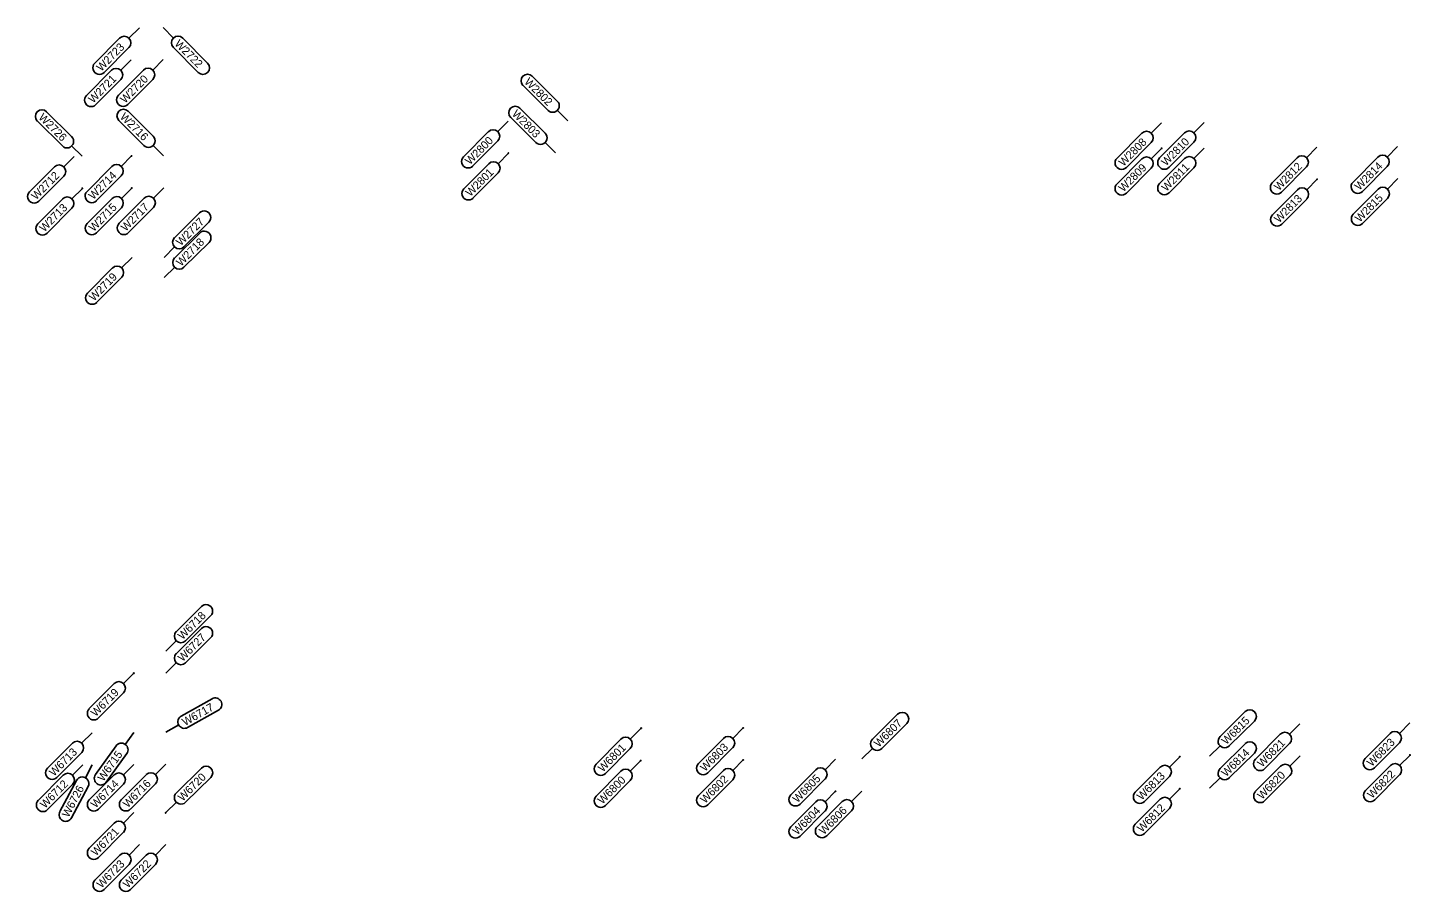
# Model space of a CAD drawing. Extents: x 12479652 to 12487250, y 9842710 to 9846560.
# Drawn here: x 12484644.7 to 12484860.6, y 9842742.5 to 9842877.4 of the extents above; entities that cross this region are included whole.
import ezdxf

# ---------------------------------------------------------------- set-up
doc = ezdxf.new("R2010")
doc.units = 0
doc.layers.add('_CIVIL_CONSTRUCTION', color=7, linetype='Continuous')
doc.layers.add('TextAlignmentLrg', color=7, linetype='Continuous')

msp = doc.modelspace()

# ---------------------------------------------------------------- linework, layer by layer
at = {"layer": '_CIVIL_CONSTRUCTION'}
for p, q in [((12484662.12, 9842877.34), (12484660.49, 9842875.71)), ((12484665.82, 9842877.36), (12484667.44, 9842875.72)), ((12484655.15, 9842871.79), (12484659.04, 9842875.7)), ((12484672.78, 9842871.81), (12484668.89, 9842875.72)), ((12484660.5, 9842874.26), (12484656.61, 9842870.34)), ((12484667.44, 9842874.27), (12484671.33, 9842870.36)), ((12484660.84, 9842872.33), (12484659.22, 9842870.7)), ((12484665.84, 9842872.36), (12484664.22, 9842870.72)), ((12484653.88, 9842866.78), (12484657.77, 9842870.7)), ((12484659.22, 9842869.25), (12484655.33, 9842865.34)), ((12484658.88, 9842866.81), (12484662.77, 9842870.72)), ((12484664.22, 9842869.27), (12484660.33, 9842865.36)), ((12484723.49, 9842869.79), (12484727.4, 9842865.9)), ((12484725.95, 9842864.44), (12484722.04, 9842868.33)), ((12484660.36, 9842864.32), (12484664.27, 9842860.43)), ((12484721.57, 9842864.77), (12484725.48, 9842860.88)), ((12484729.03, 9842862.83), (12484727.4, 9842864.45)), ((12484650.1, 9842858.88), (12484646.19, 9842862.77)), ((12484647.63, 9842864.23), (12484651.55, 9842860.34)), ((12484662.83, 9842858.98), (12484658.92, 9842862.87)), ((12484719.71, 9842862.75), (12484718.09, 9842861.12)), ((12484724.03, 9842859.43), (12484720.12, 9842863.32)), ((12484821.78, 9842862.51), (12484820.15, 9842860.88)), ((12484828.43, 9842862.56), (12484826.81, 9842860.93)), ((12484712.75, 9842857.2), (12484716.64, 9842861.12)), ((12484814.81, 9842856.96), (12484818.7, 9842860.87)), ((12484821.47, 9842857.01), (12484825.36, 9842860.92)), ((12484653.18, 9842857.27), (12484651.55, 9842858.89)), ((12484665.91, 9842857.36), (12484664.28, 9842858.98)), ((12484718.09, 9842859.67), (12484714.2, 9842855.76)), ((12484727.12, 9842857.81), (12484725.48, 9842859.43)), ((12484820.16, 9842859.43), (12484816.27, 9842855.51)), ((12484821.78, 9842858.51), (12484820.15, 9842856.88)), ((12484826.82, 9842859.47), (12484822.93, 9842855.56)), ((12484828.43, 9842858.56), (12484826.81, 9842856.93)), ((12484846.02, 9842858.69), (12484844.4, 9842857.05)), ((12484858.63, 9842858.78), (12484857.01, 9842857.15)), ((12484651.94, 9842857.25), (12484650.32, 9842855.62)), ((12484653.95, 9842851.77), (12484657.84, 9842855.68)), ((12484660.91, 9842857.32), (12484659.29, 9842855.69)), ((12484712.8, 9842852.2), (12484716.69, 9842856.12)), ((12484719.76, 9842857.75), (12484718.14, 9842856.12)), ((12484814.81, 9842852.96), (12484818.7, 9842856.87)), ((12484821.47, 9842853.01), (12484825.36, 9842856.92)), ((12484839.06, 9842853.14), (12484842.95, 9842857.05)), ((12484851.67, 9842853.23), (12484855.56, 9842857.14)), ((12484857.02, 9842855.7), (12484853.13, 9842851.78)), ((12484644.98, 9842851.7), (12484648.87, 9842855.62)), ((12484650.32, 9842854.17), (12484646.43, 9842850.26)), ((12484659.29, 9842854.24), (12484655.4, 9842850.32)), ((12484718.14, 9842854.67), (12484714.25, 9842850.76)), ((12484820.16, 9842855.42), (12484816.27, 9842851.51)), ((12484826.82, 9842855.47), (12484822.93, 9842851.56)), ((12484844.4, 9842855.6), (12484840.51, 9842851.69)), ((12484846.06, 9842853.69), (12484844.43, 9842852.06)), ((12484858.67, 9842853.78), (12484857.05, 9842852.15)), ((12484653.22, 9842852.26), (12484651.6, 9842850.63)), ((12484660.93, 9842852.32), (12484659.31, 9842850.69)), ((12484665.93, 9842852.36), (12484664.31, 9842850.72)), ((12484839.09, 9842848.14), (12484842.98, 9842852.05)), ((12484851.71, 9842848.23), (12484855.6, 9842852.14)), ((12484646.26, 9842846.71), (12484650.15, 9842850.63)), ((12484651.6, 9842849.18), (12484647.71, 9842845.27)), ((12484653.97, 9842846.77), (12484657.86, 9842850.68)), ((12484659.32, 9842849.24), (12484655.43, 9842845.32)), ((12484658.97, 9842846.81), (12484662.86, 9842850.72)), ((12484664.32, 9842849.27), (12484660.43, 9842845.36)), ((12484844.44, 9842850.6), (12484840.55, 9842846.69)), ((12484857.05, 9842850.7), (12484853.17, 9842846.78)), ((12484671.54, 9842848.45), (12484667.63, 9842844.56)), ((12484671.55, 9842845.29), (12484667.64, 9842841.4)), ((12484669.07, 9842843.11), (12484672.98, 9842847)), ((12484665.99, 9842841.49), (12484667.62, 9842843.11)), ((12484669.09, 9842839.94), (12484673, 9842843.83)), ((12484660.99, 9842841.46), (12484659.36, 9842839.83)), ((12484654.02, 9842835.91), (12484657.91, 9842839.83)), ((12484659.37, 9842838.38), (12484655.48, 9842834.47)), ((12484666, 9842838.33), (12484667.64, 9842839.95)), ((12484671.81, 9842786.98), (12484667.9, 9842783.09)), ((12484669.34, 9842781.64), (12484673.26, 9842785.53)), ((12484671.81, 9842783.54), (12484667.9, 9842779.65)), ((12484666.26, 9842780.02), (12484667.89, 9842781.64)), ((12484669.34, 9842778.19), (12484673.26, 9842782.08)), ((12484666.26, 9842776.57), (12484667.89, 9842778.2)), ((12484661.26, 9842776.57), (12484659.64, 9842774.94)), ((12484654.3, 9842771.03), (12484658.19, 9842774.94)), ((12484659.64, 9842773.49), (12484655.75, 9842769.58)), ((12484673.48, 9842772.57), (12484668.66, 9842769.88)), ((12484669.66, 9842768.08), (12484674.48, 9842770.78)), ((12484780.54, 9842770.15), (12484776.62, 9842766.28)), ((12484834.83, 9842770.56), (12484830.91, 9842766.68)), ((12484654.74, 9842767.27), (12484653.11, 9842765.64)), ((12484661.26, 9842767.32), (12484659.92, 9842765.45)), ((12484666.26, 9842767.36), (12484668.27, 9842768.48)), ((12484740.42, 9842767.91), (12484738.79, 9842766.27)), ((12484756.42, 9842768.02), (12484754.79, 9842766.39)), ((12484778.06, 9842764.82), (12484781.99, 9842768.69)), ((12484832.35, 9842765.22), (12484836.27, 9842769.1)), ((12484843.38, 9842768.67), (12484841.76, 9842767.03)), ((12484853.57, 9842763.24), (12484857.46, 9842767.16)), ((12484860.53, 9842768.79), (12484858.91, 9842767.16)), ((12484647.77, 9842761.72), (12484651.66, 9842765.64)), ((12484655.28, 9842760.73), (12484658.49, 9842765.21)), ((12484733.45, 9842762.36), (12484737.34, 9842766.27)), ((12484749.45, 9842762.48), (12484753.34, 9842766.39)), ((12484829.26, 9842763.61), (12484830.9, 9842765.23)), ((12484834.83, 9842765.55), (12484830.91, 9842761.68)), ((12484836.42, 9842763.12), (12484840.31, 9842767.03)), ((12484841.77, 9842765.58), (12484837.88, 9842761.67)), ((12484858.92, 9842765.71), (12484855.03, 9842761.8)), ((12484653.12, 9842764.19), (12484649.23, 9842760.28)), ((12484660.16, 9842764.02), (12484656.95, 9842759.53)), ((12484738.8, 9842764.82), (12484734.91, 9842760.91)), ((12484740.42, 9842762.91), (12484738.79, 9842761.27)), ((12484754.8, 9842764.94), (12484750.91, 9842761.03)), ((12484756.42, 9842763.02), (12484754.79, 9842761.39)), ((12484770.84, 9842763.13), (12484769.22, 9842761.5)), ((12484774.97, 9842763.21), (12484776.61, 9842764.83)), ((12484824.63, 9842763.53), (12484823.01, 9842761.9)), ((12484832.35, 9842760.22), (12484836.27, 9842764.1)), ((12484843.42, 9842763.67), (12484841.8, 9842762.03)), ((12484860.57, 9842763.79), (12484858.95, 9842762.16)), ((12484653.31, 9842762.26), (12484651.68, 9842760.63)), ((12484654.77, 9842762.27), (12484653.69, 9842760.24)), ((12484654.3, 9842756.77), (12484658.19, 9842760.68)), ((12484659.3, 9842756.81), (12484663.19, 9842760.72)), ((12484661.26, 9842762.32), (12484659.64, 9842760.69)), ((12484666.26, 9842762.36), (12484664.64, 9842760.73)), ((12484671.83, 9842761.75), (12484667.91, 9842757.87)), ((12484733.45, 9842757.36), (12484737.34, 9842761.27)), ((12484749.45, 9842757.48), (12484753.34, 9842761.39)), ((12484763.88, 9842757.58), (12484767.77, 9842761.49)), ((12484817.67, 9842757.98), (12484821.56, 9842761.89)), ((12484836.46, 9842758.12), (12484840.35, 9842762.03)), ((12484853.61, 9842758.24), (12484857.5, 9842762.16)), ((12484858.95, 9842760.71), (12484855.07, 9842756.8)), ((12484646.34, 9842756.71), (12484650.23, 9842760.63)), ((12484651.69, 9842759.18), (12484647.8, 9842755.27)), ((12484649.72, 9842754.95), (12484652.31, 9842759.82)), ((12484654.12, 9842758.85), (12484651.53, 9842753.98)), ((12484659.64, 9842759.24), (12484655.75, 9842755.33)), ((12484664.64, 9842759.28), (12484660.75, 9842755.36)), ((12484669.35, 9842756.41), (12484673.27, 9842760.29)), ((12484738.8, 9842759.82), (12484734.91, 9842755.91)), ((12484754.8, 9842759.94), (12484750.91, 9842756.03)), ((12484769.22, 9842760.05), (12484765.34, 9842756.14)), ((12484823.01, 9842760.45), (12484819.12, 9842756.53)), ((12484824.63, 9842758.53), (12484823.01, 9842756.9)), ((12484829.26, 9842758.61), (12484830.9, 9842760.23)), ((12484841.8, 9842760.58), (12484837.91, 9842756.67)), ((12484666.26, 9842754.8), (12484667.9, 9842756.42)), ((12484763.88, 9842752.58), (12484767.77, 9842756.49)), ((12484768.01, 9842752.61), (12484771.9, 9842756.52)), ((12484770.84, 9842758.13), (12484769.22, 9842756.5)), ((12484774.97, 9842758.16), (12484773.35, 9842756.53)), ((12484817.67, 9842752.98), (12484821.56, 9842756.89)), ((12484661.26, 9842754.8), (12484659.64, 9842753.17)), ((12484769.22, 9842755.05), (12484765.34, 9842751.13)), ((12484773.36, 9842755.08), (12484769.47, 9842751.17)), ((12484823.01, 9842755.45), (12484819.12, 9842751.53)), ((12484654.3, 9842749.25), (12484658.19, 9842753.17)), ((12484659.64, 9842751.72), (12484655.75, 9842747.81)), ((12484655.19, 9842744.25), (12484659.08, 9842748.17)), ((12484659.3, 9842744.25), (12484663.19, 9842748.17)), ((12484662.15, 9842749.8), (12484660.53, 9842748.17)), ((12484666.26, 9842749.8), (12484664.64, 9842748.17)), ((12484660.53, 9842746.72), (12484656.64, 9842742.81)), ((12484664.64, 9842746.72), (12484660.75, 9842742.81))]:
    msp.add_line(p, q, dxfattribs=at)
for centre, start, end in [((12484659.77, 9842874.98), 315.1702, 135.1702), ((12484668.16, 9842875), 44.8298, 224.8298), ((12484655.88, 9842871.07), 135.1702, 315.1702), ((12484658.49, 9842869.97), 315.1702, 135.1702), ((12484663.49, 9842870), 315.1702, 135.1702), ((12484672.05, 9842871.08), 224.8298, 44.8298), ((12484722.76, 9842869.06), 45.1702, 225.1702), ((12484654.6, 9842866.06), 135.1702, 315.1702), ((12484659.6, 9842866.08), 135.1702, 315.1702), ((12484646.91, 9842863.5), 45.1702, 225.1702), ((12484659.64, 9842863.59), 45.1702, 225.1702), ((12484720.84, 9842864.05), 45.1702, 225.1702), ((12484726.67, 9842865.17), 225.1702, 45.1702), ((12484650.82, 9842859.61), 225.1702, 45.1702), ((12484663.55, 9842859.7), 225.1702, 45.1702), ((12484717.37, 9842860.39), 315.1702, 135.1702), ((12484724.76, 9842860.16), 225.1702, 45.1702), ((12484819.43, 9842860.15), 315.1702, 135.1702), ((12484826.09, 9842860.2), 315.1702, 135.1702), ((12484649.59, 9842854.89), 315.1702, 135.1702), ((12484658.57, 9842854.96), 315.1702, 135.1702), ((12484713.48, 9842856.48), 135.1702, 315.1702), ((12484717.42, 9842855.39), 315.1702, 135.1702), ((12484815.54, 9842856.24), 135.1702, 315.1702), ((12484819.43, 9842856.15), 315.1702, 135.1702), ((12484822.2, 9842856.28), 135.1702, 315.1702), ((12484826.09, 9842856.2), 315.1702, 135.1702), ((12484843.67, 9842856.33), 315.1702, 135.1702), ((12484856.29, 9842856.42), 315.1702, 135.1702), ((12484645.7, 9842850.98), 135.1702, 315.1702), ((12484654.68, 9842851.05), 135.1702, 315.1702), ((12484713.53, 9842851.48), 135.1702, 315.1702), ((12484815.54, 9842852.24), 135.1702, 315.1702), ((12484822.2, 9842852.28), 135.1702, 315.1702), ((12484839.79, 9842852.41), 135.1702, 315.1702), ((12484843.71, 9842851.33), 315.1702, 135.1702), ((12484852.4, 9842852.51), 135.1702, 315.1702), ((12484856.33, 9842851.42), 315.1702, 135.1702), ((12484650.87, 9842849.9), 315.1702, 135.1702), ((12484658.59, 9842849.96), 315.1702, 135.1702), ((12484663.59, 9842850), 315.1702, 135.1702), ((12484672.26, 9842847.73), 314.8298, 134.8298), ((12484839.82, 9842847.41), 135.1702, 315.1702), ((12484852.44, 9842847.51), 135.1702, 315.1702), ((12484646.98, 9842845.99), 135.1702, 315.1702), ((12484654.7, 9842846.05), 135.1702, 315.1702), ((12484659.7, 9842846.08), 135.1702, 315.1702), ((12484672.28, 9842844.56), 314.8298, 134.8298), ((12484668.35, 9842843.84), 134.8298, 314.8298), ((12484668.36, 9842840.67), 134.8298, 314.8298), ((12484658.64, 9842839.1), 315.1702, 135.1702), ((12484654.75, 9842835.19), 135.1702, 315.1702), ((12484672.53, 9842786.25), 314.8298, 134.8298), ((12484668.62, 9842782.36), 134.8298, 314.8298), ((12484672.53, 9842782.81), 314.8298, 134.8298), ((12484668.62, 9842778.92), 134.8298, 314.8298), ((12484658.92, 9842774.22), 315.1702, 135.1702), ((12484673.98, 9842771.67), 299.1968, 119.1968), ((12484655.03, 9842770.3), 135.1702, 315.1702), ((12484669.16, 9842768.98), 119.1968, 299.1968), ((12484781.26, 9842769.42), 314.6453, 134.6453), ((12484835.55, 9842769.83), 314.6453, 134.6453), ((12484841.04, 9842766.31), 315.1702, 135.1702), ((12484858.19, 9842766.43), 315.1702, 135.1702), ((12484652.39, 9842764.91), 315.1702, 135.1702), ((12484659.32, 9842764.62), 324.4043, 144.4043), ((12484738.07, 9842765.55), 315.1702, 135.1702), ((12484754.07, 9842765.66), 315.1702, 135.1702), ((12484777.34, 9842765.55), 134.6453, 314.6453), ((12484831.63, 9842765.95), 134.6453, 314.6453), ((12484835.55, 9842764.83), 314.6453, 134.6453), ((12484837.15, 9842762.39), 135.1702, 315.1702), ((12484854.3, 9842762.52), 135.1702, 315.1702), ((12484648.5, 9842761), 135.1702, 315.1702), ((12484650.96, 9842759.9), 315.1702, 135.1702), ((12484656.11, 9842760.13), 144.4043, 324.4043), ((12484658.92, 9842759.96), 315.1702, 135.1702), ((12484663.92, 9842760), 315.1702, 135.1702), ((12484672.55, 9842761.02), 314.6453, 134.6453), ((12484734.18, 9842761.63), 135.1702, 315.1702), ((12484738.07, 9842760.55), 315.1702, 135.1702), ((12484750.18, 9842761.75), 135.1702, 315.1702), ((12484754.07, 9842760.66), 315.1702, 135.1702), ((12484768.5, 9842760.77), 315.1702, 135.1702), ((12484822.28, 9842761.17), 315.1702, 135.1702), ((12484831.63, 9842760.95), 134.6453, 314.6453), ((12484841.08, 9842761.31), 315.1702, 135.1702), ((12484858.23, 9842761.43), 315.1702, 135.1702), ((12484653.21, 9842759.34), 332.0007, 152.0007), ((12484647.07, 9842755.99), 135.1702, 315.1702), ((12484655.03, 9842756.05), 135.1702, 315.1702), ((12484660.03, 9842756.09), 135.1702, 315.1702), ((12484668.63, 9842757.14), 134.6453, 314.6453), ((12484734.18, 9842756.63), 135.1702, 315.1702), ((12484750.18, 9842756.75), 135.1702, 315.1702), ((12484764.61, 9842756.86), 135.1702, 315.1702), ((12484768.5, 9842755.77), 315.1702, 135.1702), ((12484772.63, 9842755.8), 315.1702, 135.1702), ((12484818.39, 9842757.26), 135.1702, 315.1702), ((12484822.28, 9842756.17), 315.1702, 135.1702), ((12484837.19, 9842757.39), 135.1702, 315.1702), ((12484854.34, 9842757.52), 135.1702, 315.1702), ((12484650.62, 9842754.46), 152.0007, 332.0007), ((12484658.92, 9842752.44), 315.1702, 135.1702), ((12484764.61, 9842751.86), 135.1702, 315.1702), ((12484768.74, 9842751.89), 135.1702, 315.1702), ((12484818.39, 9842752.26), 135.1702, 315.1702), ((12484655.03, 9842748.53), 135.1702, 315.1702), ((12484659.81, 9842747.44), 315.1702, 135.1702), ((12484663.92, 9842747.44), 315.1702, 135.1702), ((12484655.92, 9842743.53), 135.1702, 315.1702), ((12484660.03, 9842743.53), 135.1702, 315.1702)]:
    msp.add_arc(centre, 1.03, start, end, dxfattribs=at)
at = {"layer": 'TextAlignmentLrg'}
for centre in [(12484719.76, 9842857.76), (12484821.78, 9842858.51), (12484660.91, 9842857.32), (12484846.06, 9842853.69), (12484653.22, 9842852.26), (12484660.94, 9842852.32), (12484661.26, 9842776.57), (12484740.5, 9842767.99), (12484756.42, 9842768.02), (12484740.42, 9842762.91), (12484756.42, 9842763.02), (12484824.63, 9842763.53), (12484860.57, 9842763.79), (12484824.63, 9842758.53), (12484770.84, 9842758.13), (12484666.22, 9842754.76)]:
    msp.add_circle(centre, 0.05, dxfattribs=at)

# ---------------------------------------------------------------- texts
at = {"layer": '_CIVIL_CONSTRUCTION'}
for s, rotation, p in [('W2722', 314.8298, (12484667.53, 9842874.73)), ('W2723', 45.1702, (12484656.16, 9842870.45)), ('W2721', 45.1702, (12484654.91, 9842865.47)), ('W2720', 45.1702, (12484659.88, 9842865.46)), ('W2802', 315.1702, (12484722.15, 9842868.77)), ('W2803', 315.1702, (12484720.22, 9842863.77)), ('W2726', 315.1702, (12484646.28, 9842863.23)), ('W2716', 315.1702, (12484659.01, 9842863.32)), ('W2800', 45.1702, (12484713.75, 9842855.85)), ('W2808', 45.1702, (12484815.81, 9842855.61)), ('W2810', 45.1702, (12484822.47, 9842855.66)), ('W2809', 45.1702, (12484815.81, 9842851.61)), ('W2811', 45.1702, (12484822.51, 9842851.69)), ('W2812', 45.1702, (12484840.08, 9842851.81)), ('W2814', 45.1702, (12484852.67, 9842851.87)), ('W2712', 45.1702, (12484646, 9842850.37)), ('W2714', 45.1702, (12484654.94, 9842850.41)), ('W2801', 45.1702, (12484713.83, 9842850.89)), ('W2815', 45.1702, (12484852.72, 9842846.89)), ('W2713', 45.1702, (12484647.26, 9842845.37)), ('W2715', 45.1702, (12484654.98, 9842845.43)), ('W2717', 45.1702, (12484659.98, 9842845.47)), ('W2813', 45.1702, (12484840.1, 9842846.79)), ('W2727', 44.8298, (12484668.6, 9842843.19)), ('W2718', 44.8298, (12484668.61, 9842840.02)), ('W2719', 45.1702, (12484655.02, 9842834.57)), ('W6718', 44.8298, (12484668.86, 9842781.71)), ('W6727', 44.8298, (12484668.87, 9842778.28)), ('W6719', 45.1702, (12484655.3, 9842769.68)), ('W6717', 29.1968, (12484669.24, 9842768.29)), ('W6807', 44.6453, (12484777.59, 9842764.91)), ('W6815', 44.6453, (12484831.88, 9842765.31)), ('W6801', 45.1702, (12484734.49, 9842761.04)), ('W6803', 45.1702, (12484750.46, 9842761.13)), ('W6821', 45.1702, (12484837.46, 9842761.8)), ('W6823', 45.1702, (12484854.58, 9842761.9)), ('W6713', 45.1702, (12484648.78, 9842760.38)), ('W6715', 54.4043, (12484656.49, 9842759.57)), ('W6814', 44.6453, (12484831.86, 9842760.29)), ('W6720', 44.6453, (12484668.87, 9842756.49)), ('W6805', 45.1702, (12484764.89, 9842756.24)), ('W6813', 45.1702, (12484818.67, 9842756.64)), ('W6820', 45.1702, (12484837.46, 9842756.77)), ('W6822', 45.1702, (12484854.63, 9842756.91)), ('W6712', 45.1702, (12484647.36, 9842755.38)), ('W6726', 62.0007, (12484651.06, 9842753.94)), ('W6714', 45.1702, (12484655.29, 9842755.41)), ('W6716', 45.1702, (12484660.3, 9842755.46)), ('W6800', 45.1702, (12484734.45, 9842756.01)), ('W6802', 45.1702, (12484750.47, 9842756.14)), ('W6804', 45.1702, (12484764.87, 9842751.22)), ('W6806', 45.1702, (12484769.01, 9842751.26)), ('W6812', 45.1702, (12484818.69, 9842751.65)), ('W6721', 45.1702, (12484655.33, 9842747.94)), ('W6723', 45.1702, (12484656.2, 9842742.91)), ('W6722', 45.1702, (12484660.32, 9842742.92))]:
    msp.add_text(s, height=1.25, rotation=rotation, dxfattribs=at).set_placement(p)

doc.saveas('drawing.dxf')
